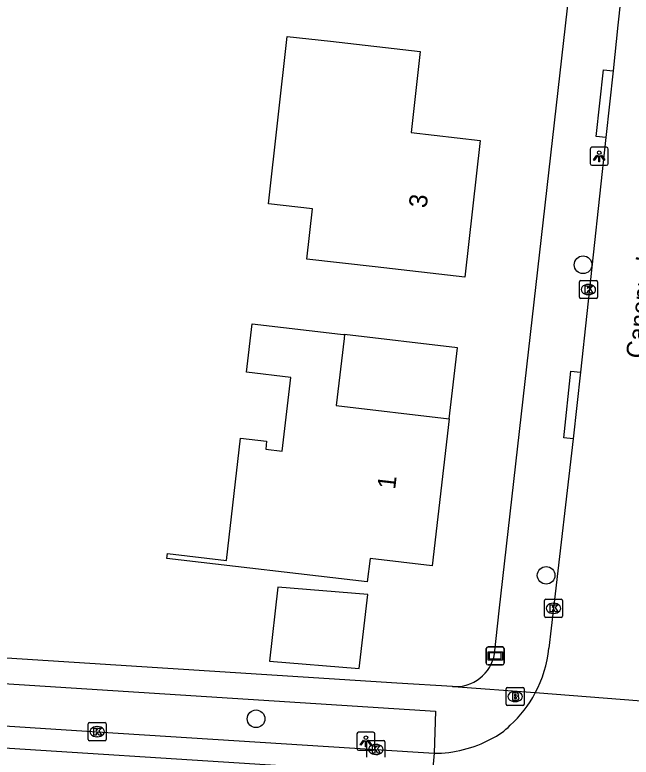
# Model space of a CAD drawing. Extents: x 162398 to 163643, y 386453 to 387397.
# Drawn here: x 162753.98 to 162788.12, y 386597.2 to 386638.31 of the extents above; entities that cross this region are included whole.
import ezdxf

# ---------------------------------------------------------------- set-up
doc = ezdxf.new("R2010")
doc.units = 0
for name, color, linetype in [('IMGEO_Boom', 7, 'Continuous'), ('IMGEO_Brandkraan', 7, 'Continuous'), ('IMGEO_Kolk', 7, 'Continuous'), ('IMGEO_Lichtpunt', 7, 'Continuous'), ('IMGEO_Openbare_ruimte_label', 7, 'Continuous'), ('IMGEO_Pand', 7, 'Continuous'), ('IMGEO_Pand_nummerreeks', 7, 'Continuous'), ('IMGEO_Pand_overbouw', 7, 'Continuous'), ('IMGEO_Rijbaan_lokaal_gesloten', 7, 'Continuous'), ('IMGEO_Rijbaan_lokaal_open', 7, 'Continuous'), ('IMGEO_Verklikker', 7, 'Continuous'), ('IMGEO_Voetpad_open', 7, 'Continuous')]:
    doc.layers.add(name, color=color, linetype=linetype)

msp = doc.modelspace()

# ---------------------------------------------------------------- linework, layer by layer
at = {"layer": 'IMGEO_Boom'}
for centre in [(162785.458, 386624.47), (162783.413, 386607.271), (162767.342, 386599.325)]:
    msp.add_circle(centre, 0.489, dxfattribs=at)
at = {"layer": 'IMGEO_Brandkraan'}
for p, q in [((162781.194, 386600.132), (162781.194, 386600.984)), ((162781.269, 386601.058), (162782.121, 386601.058)), ((162782.195, 386600.984), (162782.195, 386600.132)), ((162781.682, 386600.838), (162781.707, 386600.838)), ((162781.705, 386600.278), (162781.68, 386600.278)), ((162782.121, 386600.058), (162781.269, 386600.058))]:
    msp.add_line(p, q, dxfattribs=at)
for points in [[(162781.194, 386600.132), (162781.194, 386600.984)], [(162781.269, 386601.058), (162782.121, 386601.058)], [(162782.195, 386600.984), (162782.195, 386600.132)], [(162781.542, 386600.758), (162781.542, 386600.358), (162781.755, 386600.358)], [(162781.773, 386600.758), (162781.542, 386600.758)], [(162781.721, 386600.677), (162781.667, 386600.677), (162781.667, 386600.601)], [(162781.667, 386600.601), (162781.72, 386600.601)], [(162781.729, 386600.525), (162781.667, 386600.525), (162781.667, 386600.444)], [(162781.667, 386600.444), (162781.729, 386600.444)], [(162782.121, 386600.058), (162781.269, 386600.058)]]:
    msp.add_lwpolyline(points, dxfattribs=at)
for centre, radius, start, end in [((162781.271, 386600.982), 0.0765, 91.552, 178.448), ((162781.271, 386600.982), 0.0765, 91.552, 178.448), ((162782.119, 386600.982), 0.0765, 1.552, 88.448), ((162782.119, 386600.982), 0.0765, 1.552, 88.448), ((162781.722, 386600.639), 0.0379, 267.8285, 90.9355), ((162781.73, 386600.484), 0.0404, 269.8759, 90.5077), ((162781.777, 386600.613), 0.145, 59.4692, 91.5367), ((162781.802, 386600.66), 0.0922, 285.5137, 58.1501), ((162781.807, 386600.468), 0.105, 301.3115, 78.989), ((162781.271, 386600.134), 0.0765, 181.552, 268.448), ((162781.271, 386600.134), 0.0765, 181.552, 268.448), ((162781.761, 386600.609), 0.251, 268.6676, 293.5347), ((162782.119, 386600.134), 0.0765, 271.552, 358.448), ((162782.119, 386600.134), 0.0765, 271.552, 358.448)]:
    msp.add_arc(centre, radius, start, end, dxfattribs=at)
for centre, major_axis, ratio, start_param, end_param in [((162781.681, 386600.558), (-0.387, 0.002), 0.722429, 4.712389, 7.853982), ((162781.706, 386600.558), (-0.39, 0.002), 0.717154, 1.570796, 4.712389)]:
    msp.add_ellipse(centre, major_axis=major_axis, ratio=ratio, start_param=start_param, end_param=end_param, dxfattribs=at)
at = {"layer": 'IMGEO_Kolk'}
for p, q in [((162785.253, 386622.675), (162785.253, 386623.527)), ((162785.328, 386623.601), (162786.18, 386623.601)), ((162786.254, 386623.527), (162786.254, 386622.675)), ((162785.741, 386623.381), (162785.766, 386623.381)), ((162785.764, 386622.821), (162785.739, 386622.821)), ((162786.18, 386622.601), (162785.328, 386622.601)), ((162783.316, 386605.019), (162783.316, 386605.871)), ((162783.391, 386605.945), (162784.243, 386605.945)), ((162784.317, 386605.871), (162784.317, 386605.019)), ((162783.804, 386605.725), (162783.829, 386605.725)), ((162783.827, 386605.165), (162783.802, 386605.165)), ((162784.243, 386604.945), (162783.391, 386604.945)), ((162758.039, 386598.187), (162758.039, 386599.039)), ((162758.114, 386599.113), (162758.966, 386599.113)), ((162758.527, 386598.893), (162758.552, 386598.893)), ((162759.04, 386599.039), (162759.04, 386598.187)), ((162758.966, 386598.113), (162758.114, 386598.113)), ((162758.55, 386598.333), (162758.525, 386598.333)), ((162773.479, 386597.202), (162773.479, 386598.054)), ((162773.554, 386598.128), (162774.406, 386598.128)), ((162774.48, 386598.054), (162774.48, 386597.202)), ((162773.967, 386597.908), (162773.992, 386597.908)), ((162773.99, 386597.348), (162773.965, 386597.348))]:
    msp.add_line(p, q, dxfattribs=at)
for points in [[(162785.253, 386622.675), (162785.253, 386623.527)], [(162785.328, 386623.601), (162786.18, 386623.601)], [(162786.254, 386623.527), (162786.254, 386622.675)], [(162785.574, 386623.301), (162785.697, 386623.301), (162785.697, 386623.15), (162785.827, 386623.301), (162785.991, 386623.301), (162785.845, 386623.15), (162785.998, 386622.901), (162785.846, 386622.901), (162785.761, 386623.065), (162785.697, 386622.998), (162785.697, 386622.901), (162785.574, 386622.901), (162785.574, 386623.301)], [(162786.18, 386622.601), (162785.328, 386622.601)], [(162783.316, 386605.019), (162783.316, 386605.871)], [(162783.391, 386605.945), (162784.243, 386605.945)], [(162784.317, 386605.871), (162784.317, 386605.019)], [(162783.637, 386605.645), (162783.76, 386605.645), (162783.76, 386605.494), (162783.89, 386605.645), (162784.054, 386605.645), (162783.908, 386605.494), (162784.061, 386605.245), (162783.909, 386605.245), (162783.824, 386605.409), (162783.76, 386605.342), (162783.76, 386605.245), (162783.637, 386605.245), (162783.637, 386605.645)], [(162784.243, 386604.945), (162783.391, 386604.945)], [(162758.039, 386598.187), (162758.039, 386599.039)], [(162758.114, 386599.113), (162758.966, 386599.113)], [(162759.04, 386599.039), (162759.04, 386598.187)], [(162758.36, 386598.813), (162758.483, 386598.813), (162758.483, 386598.662), (162758.613, 386598.813), (162758.777, 386598.813), (162758.631, 386598.662), (162758.784, 386598.413), (162758.632, 386598.413), (162758.547, 386598.577), (162758.483, 386598.51), (162758.483, 386598.413), (162758.36, 386598.413), (162758.36, 386598.813)], [(162758.966, 386598.113), (162758.114, 386598.113)], [(162773.479, 386597.202), (162773.479, 386598.054)], [(162773.554, 386598.128), (162774.406, 386598.128)], [(162774.48, 386598.054), (162774.48, 386597.202)], [(162773.8, 386597.828), (162773.923, 386597.828), (162773.923, 386597.677), (162774.053, 386597.828), (162774.217, 386597.828), (162774.071, 386597.677), (162774.224, 386597.428), (162774.072, 386597.428), (162773.987, 386597.592), (162773.923, 386597.525), (162773.923, 386597.428), (162773.8, 386597.428), (162773.8, 386597.828)]]:
    msp.add_lwpolyline(points, dxfattribs=at)
for centre, start, end in [((162785.33, 386623.525), 91.552, 178.448), ((162785.33, 386623.525), 91.552, 178.448), ((162786.178, 386623.525), 1.552, 88.448), ((162786.178, 386623.525), 1.552, 88.448), ((162785.33, 386622.677), 181.552, 268.448), ((162785.33, 386622.677), 181.552, 268.448), ((162786.178, 386622.677), 271.552, 358.448), ((162786.178, 386622.677), 271.552, 358.448), ((162783.393, 386605.869), 91.552, 178.448), ((162783.393, 386605.869), 91.552, 178.448), ((162784.241, 386605.869), 1.552, 88.448), ((162784.241, 386605.869), 1.552, 88.448), ((162783.393, 386605.021), 181.552, 268.448), ((162783.393, 386605.021), 181.552, 268.448), ((162784.241, 386605.021), 271.552, 358.448), ((162784.241, 386605.021), 271.552, 358.448), ((162758.116, 386599.037), 91.552, 178.448), ((162758.116, 386599.037), 91.552, 178.448), ((162758.964, 386599.037), 1.552, 88.448), ((162758.964, 386599.037), 1.552, 88.448), ((162758.116, 386598.189), 181.552, 268.448), ((162758.116, 386598.189), 181.552, 268.448), ((162758.964, 386598.189), 271.552, 358.448), ((162758.964, 386598.189), 271.552, 358.448), ((162773.556, 386598.052), 91.552, 178.448), ((162773.556, 386598.052), 91.552, 178.448), ((162774.404, 386598.052), 1.552, 88.448), ((162774.404, 386598.052), 1.552, 88.448)]:
    msp.add_arc(centre, 0.0765, start, end, dxfattribs=at)
for centre, major_axis, ratio, start_param, end_param in [((162785.74, 386623.101), (-0.387, 0.002), 0.722429, 4.712389, 7.853982), ((162785.765, 386623.101), (-0.39, 0.002), 0.717154, 1.570796, 4.712389), ((162783.803, 386605.445), (-0.387, 0.002), 0.722429, 4.712389, 7.853982), ((162783.828, 386605.445), (-0.39, 0.002), 0.717154, 1.570796, 4.712389), ((162758.526, 386598.613), (-0.387, 0.002), 0.722429, 4.712389, 7.853982), ((162758.551, 386598.613), (-0.39, 0.002), 0.717154, 1.570796, 4.712389), ((162773.966, 386597.628), (-0.387, 0.002), 0.722429, 4.712389, 7.853982), ((162773.991, 386597.628), (-0.39, 0.002), 0.717154, 1.570796, 4.712389)]:
    msp.add_ellipse(centre, major_axis=major_axis, ratio=ratio, start_param=start_param, end_param=end_param, dxfattribs=at)
at = {"layer": 'IMGEO_Lichtpunt'}
for p, q in [((162786.756, 386630.976), (162785.948, 386630.976)), ((162786.756, 386630.976), (162785.948, 386630.976)), ((162785.854, 386630.881), (162785.854, 386630.074)), ((162785.854, 386630.881), (162785.854, 386630.074)), ((162786.85, 386630.074), (162786.85, 386630.881)), ((162786.85, 386630.074), (162786.85, 386630.881)), ((162785.948, 386629.98), (162786.756, 386629.98)), ((162785.948, 386629.98), (162786.756, 386629.98)), ((162772.927, 386598.485), (162772.927, 386597.678)), ((162772.927, 386598.485), (162772.927, 386597.678)), ((162773.829, 386598.58), (162773.021, 386598.58)), ((162773.829, 386598.58), (162773.021, 386598.58)), ((162773.923, 386597.678), (162773.923, 386598.485)), ((162773.923, 386597.678), (162773.923, 386598.485)), ((162773.021, 386597.584), (162773.829, 386597.584)), ((162773.021, 386597.584), (162773.829, 386597.584))]:
    msp.add_line(p, q, dxfattribs=at)
for points in [[(162786.228, 386630.545), (162786.267, 386630.517), (162786.079, 386630.255), (162786.041, 386630.282), (162786.228, 386630.545)], [(162786.44, 386630.517), (162786.478, 386630.544), (162786.665, 386630.282), (162786.626, 386630.254), (162786.44, 386630.517)], [(162786.33, 386630.497), (162786.377, 386630.497), (162786.377, 386630.175), (162786.33, 386630.175), (162786.33, 386630.497)], [(162773.301, 386598.149), (162773.34, 386598.121), (162773.152, 386597.859), (162773.114, 386597.886), (162773.301, 386598.149)], [(162773.403, 386598.101), (162773.45, 386598.101), (162773.45, 386597.779), (162773.403, 386597.779), (162773.403, 386598.101)], [(162773.513, 386598.121), (162773.551, 386598.148), (162773.738, 386597.886), (162773.699, 386597.858), (162773.513, 386598.121)]]:
    msp.add_lwpolyline(points, dxfattribs=at)
for centre in [(162786.353, 386630.679), (162773.426, 386598.283)]:
    msp.add_circle(centre, 0.0994, dxfattribs=at)
for centre, start, end in [((162785.948, 386630.881), 90, 180), ((162785.948, 386630.881), 90, 180), ((162786.756, 386630.881), 0, 90), ((162786.756, 386630.881), 0, 90), ((162785.948, 386630.074), 180, 270), ((162785.948, 386630.074), 180, 270), ((162786.756, 386630.074), 270, 0), ((162786.756, 386630.074), 270, 360), ((162773.021, 386598.485), 90, 180), ((162773.021, 386598.485), 90, 180), ((162773.829, 386598.485), 0, 90), ((162773.829, 386598.485), 0, 90), ((162773.021, 386597.678), 180, 270), ((162773.021, 386597.678), 180, 270), ((162773.829, 386597.678), 270, 0), ((162773.829, 386597.678), 270, 360)]:
    msp.add_arc(centre, 0.0946, start, end, dxfattribs=at)
at = {"layer": 'IMGEO_Pand'}
for points in [[(162769.07, 386637.115), (162771.465, 386636.846), (162776.433, 386636.287), (162775.928, 386631.79), (162779.75, 386631.361), (162778.899, 386623.792), (162773.931, 386624.35), (162770.152, 386624.775), (162770.466, 386627.564), (162768.027, 386627.838), (162769.07, 386637.115)], [(162772.016, 386620.631), (162772.191, 386620.611), (162772.246, 386620.605), (162772.22, 386620.382), (162771.788, 386616.674), (162778.043, 386615.946), (162777.095, 386607.804), (162773.657, 386608.205), (162773.506, 386606.909), (162762.398, 386608.202), (162762.431, 386608.483), (162765.697, 386608.102), (162766.485, 386614.871), (162767.927, 386614.703), (162767.876, 386614.261), (162768.79, 386614.154), (162769.265, 386618.232), (162766.811, 386618.517), (162767.124, 386621.2), (162772.016, 386620.631)], [(162768.555, 386606.611), (162768.078, 386602.51), (162773.053, 386602.11), (162773.531, 386606.211), (162768.555, 386606.611)]]:
    msp.add_lwpolyline(points, dxfattribs=at)
at = {"layer": 'IMGEO_Pand_overbouw'}
msp.add_lwpolyline([(162778.501, 386619.876), (162772.246, 386620.605), (162772.22, 386620.382), (162771.788, 386616.674), (162778.043, 386615.946)], close=True, dxfattribs=at)
at = {"layer": 'IMGEO_Rijbaan_lokaal_gesloten'}
for points in [[(162729.676, 386600.429), (162733.128, 386600.228), (162743.097, 386599.597), (162758.54, 386598.613), (162773.98, 386597.628), (162777.205, 386597.414)], [(162777.205, 386597.414), (162777.106, 386596.182), (162742.964, 386598.357), (162729.614, 386599.202)]]:
    msp.add_lwpolyline(points, dxfattribs=at)
at = {"layer": 'IMGEO_Rijbaan_lokaal_open'}
for points in [[(162788.796, 386650.757), (162787.792, 386641.469), (162787.39, 386637.74), (162787.117, 386635.214)], [(162787.117, 386635.214), (162786.717, 386631.512)], [(162786.717, 386631.512), (162785.313, 386618.521)], [(162785.313, 386618.521), (162784.915, 386614.835)], [(162784.915, 386614.835), (162783.817, 386605.445), (162783.558, 386603.229)], [(162788.689, 386600.3), (162782.811, 386600.756)]]:
    msp.add_lwpolyline(points, dxfattribs=at)
for centre, radius, start, end in [((162776.886, 386603.895), 6.706, 332.0862, 354.2987), ((162776.923, 386603.883), 6.667, 312.4635, 332.0261), ((162778.553, 386601.853), 4.073, 296.5819, 314.8337), ((162777.168, 386604.265), 6.851, 270.3121, 297.9134)]:
    msp.add_arc(centre, radius, start, end, dxfattribs=at)
at = {"layer": 'IMGEO_Verklikker'}
for p, q in [((162780.098, 386602.411), (162780.098, 386603.211)), ((162780.098, 386603.211), (162780.098, 386602.411)), ((162780.198, 386603.311), (162780.988, 386603.311)), ((162780.988, 386603.311), (162780.198, 386603.311)), ((162781.088, 386603.211), (162781.088, 386602.411)), ((162781.088, 386602.411), (162781.088, 386603.211)), ((162780.988, 386602.311), (162780.198, 386602.311)), ((162780.198, 386602.311), (162780.988, 386602.311))]:
    msp.add_line(p, q, dxfattribs=at)
for points in [[(162780.199, 386603.043), (162780.987, 386603.043), (162780.987, 386602.579), (162780.199, 386602.579), (162780.199, 386603.043)], [(162780.264, 386602.978), (162780.264, 386602.644), (162780.922, 386602.644), (162780.922, 386602.978), (162780.264, 386602.978)]]:
    msp.add_lwpolyline(points, dxfattribs=at)
for centre, start, end in [((162780.198, 386603.211), 90, 180), ((162780.198, 386603.211), 90, 180), ((162780.988, 386603.211), 0, 90), ((162780.988, 386603.211), 360, 90), ((162780.198, 386602.411), 180, 270), ((162780.198, 386602.411), 180, 270), ((162780.988, 386602.411), 270, 0), ((162780.988, 386602.411), 270, 0)]:
    msp.add_arc(centre, 0.1, start, end, dxfattribs=at)
at = {"layer": 'IMGEO_Voetpad_open'}
for points in [[(162780.556, 386602.933), (162780.807, 386605.308), (162786.017, 386651.238)], [(162786.717, 386631.512), (162786.177, 386631.573), (162786.586, 386635.274), (162787.117, 386635.214)], [(162784.915, 386614.835), (162784.387, 386614.892), (162784.776, 386618.579), (162785.313, 386618.521)], [(162778.233, 386601.111), (162775.14, 386601.306), (162731.31, 386604.112), (162729.324, 386604.246)], [(162728.827, 386600.5), (162728.986, 386602.84), (162742.954, 386601.941), (162777.289, 386599.753), (162777.205, 386597.414)], [(162782.811, 386600.756), (162778.278, 386601.099), (162778.233, 386601.111)]]:
    msp.add_lwpolyline(points, dxfattribs=at)
msp.add_arc((162778.383, 386603.312), 2.206, 266.1117, 350.1046, dxfattribs=at)

# ---------------------------------------------------------------- texts
at = {"layer": 'IMGEO_Openbare_ruimte_label'}
msp.add_text('Canopuslaan', height=1, rotation=83.6851, dxfattribs=at).set_placement((162788.822, 386619.244))
at = {"layer": 'IMGEO_Pand_nummerreeks'}
for s, rotation, p in [('3', 83.585, (162776.79, 386627.585)), ('1', 83.3596, (162775.047, 386612.005))]:
    msp.add_text(s, height=1, rotation=rotation, dxfattribs=at).set_placement(p)

doc.saveas('drawing.dxf')
